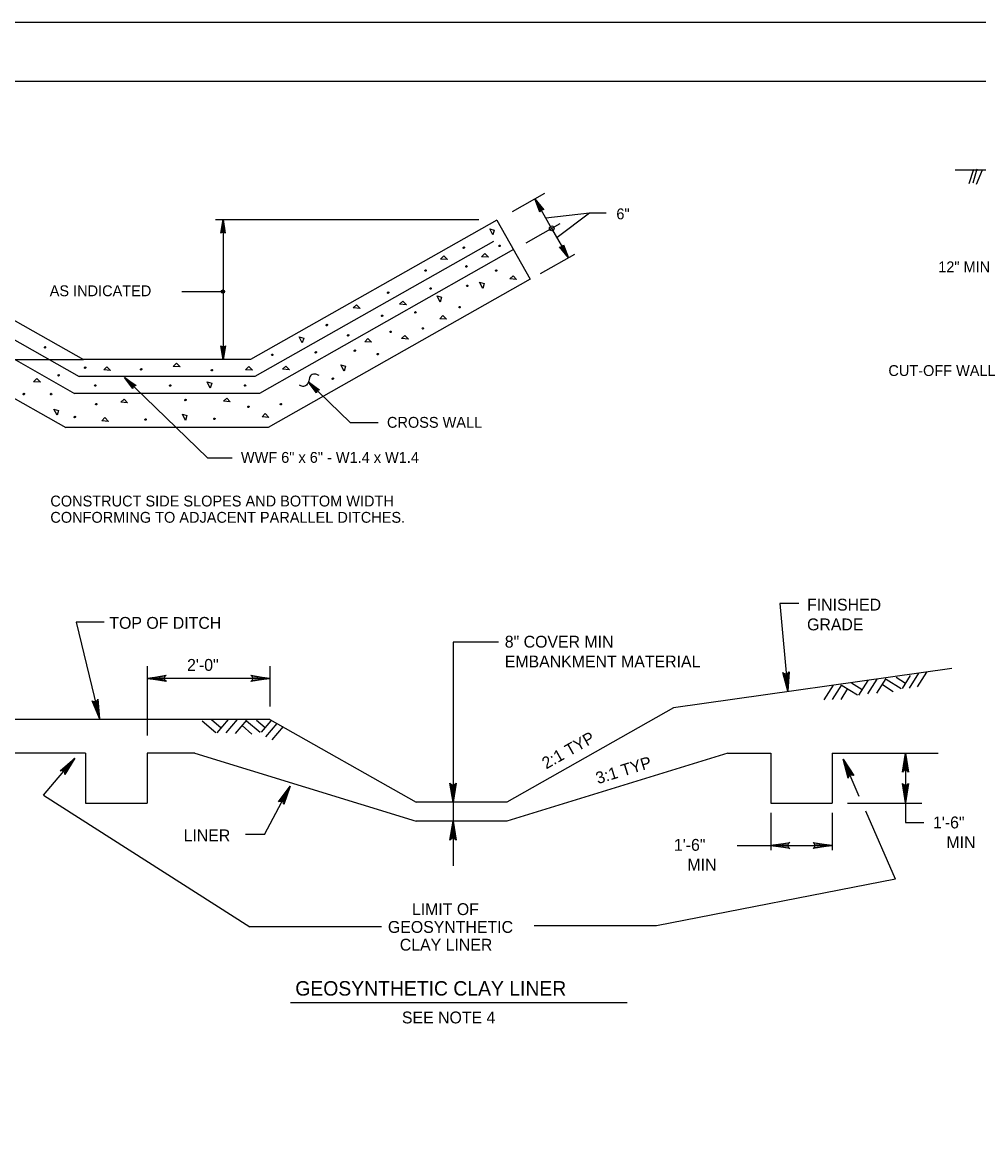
# Model space of a CAD drawing. Extents: x 5 to 910, y -47 to 547.
# Drawn here: x 364.1 to 606.1, y 266.3 to 547.5 of the extents above; entities that cross this region are included whole.
import ezdxf

# ---------------------------------------------------------------- set-up
doc = ezdxf.new("R2010")
doc.units = 0
for name, color, linetype in [('1', 7, 'Continuous'), ('2', 7, 'Continuous'), ('3', 7, 'Continuous'), ('PLT-BNDY', 7, 'Continuous')]:
    doc.layers.add(name, color=color, linetype=linetype)

msp = doc.modelspace()

# ---------------------------------------------------------------- linework, layer by layer
at = {"layer": '1'}
for p, q in [((623.41, 510.09), (600.07, 510.09)), ((604.72, 510.23), (603.5, 506.59)), ((605.54, 510.3), (604.53, 506.75)), ((606.89, 510.02), (605.36, 506.39))]:
    msp.add_line(p, q, dxfattribs=at)
msp.add_lwpolyline([(830.72, -31.53), (830.72, 532.47), (44.72, 532.47), (44.72, -31.53), (830.72, -31.53), (830.72, -5.17), (630.72, -5.17), (630.72, 59.51), (830.72, 59.51), (830.72, 88.47), (630.72, 88.47), (630.72, -31.53), (709.52, -31.53), (709.52, -5.17), (709.52, -31.53), (786.52, -31.53), (786.52, -5.17), (786.52, -17.48), (830.72, -17.48)], dxfattribs=at)
for points in [[(483.5, 494.91), (483.16, 493.68), (482.36, 495.23)], [(470.71, 488.35), (471.63, 487.41), (469.89, 487.55)], [(481.12, 488.94), (482.04, 488), (480.3, 488.14)], [(480.92, 481.37), (480.57, 480.13), (479.77, 481.69)], [(488.24, 483.34), (489.15, 482.4), (487.42, 482.53)], [(470.16, 477.91), (469.82, 476.68), (469.02, 478.23)], [(448.61, 476.01), (449.53, 475.08), (447.79, 475.21)], [(460.37, 476.95), (461.29, 476.01), (459.55, 476.15)], [(470.51, 473.27), (471.42, 472.33), (469.68, 472.47)], [(435.28, 467.57), (434.93, 466.34), (434.13, 467.89)], [(451.54, 467.46), (452.46, 466.52), (450.72, 466.66)], [(460.88, 468.24), (461.79, 467.3), (460.05, 467.43)], [(403.08, 461.21), (404, 460.27), (402.26, 460.41)], [(385.51, 460.32), (386.43, 459.38), (384.69, 459.52)], [(421.41, 460.37), (422.33, 459.43), (420.59, 459.56)], [(430.75, 460.5), (431.66, 459.56), (429.92, 459.7)], [(445.82, 460.48), (445.48, 459.24), (444.68, 460.8)], [(367.78, 457.35), (368.7, 456.41), (366.96, 456.54)], [(412.01, 456.16), (411.66, 454.92), (410.86, 456.48)], [(389.84, 452.13), (390.75, 451.19), (389.01, 451.33)], [(415.81, 452.4), (416.72, 451.47), (414.98, 451.6)], [(373.23, 449.27), (372.89, 448.03), (372.08, 449.59)], [(385.01, 447.44), (385.93, 446.5), (384.19, 446.64)], [(405.74, 447.99), (405.4, 446.75), (404.59, 448.31)], [(425.57, 448.45), (426.49, 447.51), (424.75, 447.64)]]:
    msp.add_lwpolyline(points, close=True, dxfattribs=at)
for centre in [(475.79, 490.45), (484.83, 490.89), (466.11, 484.64), (476.43, 485.71), (483.96, 484.64), (476.66, 480.77), (456.64, 479.06), (467.39, 480.11), (474.72, 475.37), (455.13, 473.22), (463.53, 474.09), (441.13, 470.87), (465.45, 470.02), (446.51, 468.26), (457.28, 469.13), (369.84, 465.24), (438.34, 463.96), (448.24, 464.39), (427.33, 463.32), (454.03, 463.52), (373.29, 458.15), (379.98, 460.09), (394.18, 459.66), (412.05, 459.45), (382.56, 455.56), (401.5, 455.56), (420.45, 455.58), (442.64, 457.3), (364.49, 453.41), (371.37, 453.41), (382.79, 450.83), (405.37, 451.9), (421.32, 450.18), (429.51, 450.85), (377.39, 447.6), (395.26, 446.96), (412.71, 447.16)]:
    msp.add_ellipse(centre, major_axis=(-0.048, -0.184), ratio=0.9, dxfattribs=at)
at = {"layer": '2'}
for p, q in [((496.2, 504.11), (488.01, 499.49)), ((493.78, 502.78), (498.01, 495.32)), ((507.6, 499.25), (511.82, 499.25)), ((318.05, 496.95), (379.59, 462.15)), ((413.01, 497.57), (479.55, 497.57)), ((414.89, 497.57), (414.89, 462.15)), ((484.17, 497.41), (421.8, 462.15)), ((484.17, 497.41), (492.61, 482.47)), ((500.11, 496.51), (491.44, 491.62)), ((498.01, 495.32), (502.24, 487.87)), ((313.84, 489.49), (377.32, 453.59)), ((318.43, 491.8), (378.44, 457.87)), ((483.32, 492.01), (422.94, 457.87)), ((488.38, 489.95), (424.06, 453.59)), ((503.75, 488.71), (495.08, 483.82)), ((309.6, 482.01), (375.08, 444.99)), ((492.61, 482.47), (426.31, 444.99)), ((404.46, 479.35), (414.89, 479.35)), ((290.57, 462.15), (379.59, 462.15)), ((421.8, 462.15), (379.59, 462.15)), ((421.8, 462.15), (379.59, 462.15)), ((421.8, 462.15), (379.59, 462.15)), ((422.94, 457.87), (378.44, 457.87)), ((389.95, 457.62), (410.93, 437.28)), ((436.44, 456.54), (447.03, 446.25)), ((424.06, 453.59), (377.32, 453.59)), ((426.31, 444.99), (375.08, 444.99)), ((447.03, 446.25), (454.15, 446.25)), ((410.93, 437.28), (417.22, 437.28)), ((560.52, 400.42), (555.74, 400.42)), ((555.74, 400.42), (557.73, 378.21)), ((384.78, 395.74), (377.74, 395.74)), ((484.56, 390.65), (473.06, 390.65)), ((473.06, 390.65), (473.06, 350.14)), ((395.67, 384.53), (395.67, 367.01)), ((426.73, 384.53), (426.73, 374.34)), ((599.2, 384), (528.85, 374)), ((426.73, 381.48), (395.67, 381.48)), ((528.85, 374), (486.65, 350.14)), ((426.73, 371.06), (357.43, 371.06)), ((426.73, 371.06), (463.73, 350.14)), ((380.12, 362.6), (357.86, 362.6)), ((380.12, 362.6), (380.12, 349.91)), ((395.67, 362.6), (395.67, 349.91)), ((407.78, 362.6), (395.67, 362.6)), ((407.78, 362.6), (463.73, 345.39)), ((542.6, 362.6), (486.65, 345.39)), ((542.6, 362.6), (553.43, 362.6)), ((553.43, 362.6), (553.43, 349.91)), ((568.98, 362.6), (595.77, 362.6)), ((568.98, 362.6), (568.98, 349.91)), ((587.54, 362.6), (587.54, 345.02)), ((380.12, 349.91), (395.67, 349.91)), ((486.65, 350.14), (463.73, 350.14)), ((473.06, 350.14), (473.06, 345.39)), ((553.43, 349.91), (568.98, 349.91)), ((572.88, 349.91), (591.66, 349.91)), ((553.43, 347.46), (553.43, 337.99)), ((568.98, 347.46), (568.98, 337.99)), ((486.65, 345.39), (463.73, 345.39)), ((473.06, 345.39), (473.06, 334.02)), ((587.54, 345.02), (592.18, 345.02)), ((425.4, 341.98), (420.52, 341.98)), ((544.9, 339.22), (568.98, 339.22)), ((454.95, 318.61), (421.68, 318.61)), ((524.51, 318.87), (493.6, 318.87)), ((517.1, 299.37), (431.97, 299.37))]:
    msp.add_line(p, q, dxfattribs=at)
msp.add_circle((414.85, 479.33), 0.409, dxfattribs=at)
at = {"layer": '3'}
for p, q in [((496.57, 497.97), (507.6, 499.25)), ((499.41, 493.06), (507.6, 499.25)), ((377.74, 395.74), (383.62, 371.29)), ((590.84, 382.77), (588.48, 379.03)), ((592.83, 383.07), (590.46, 379.33)), ((569.2, 379.77), (566.84, 376.03)), ((571.34, 379.87), (568.98, 376.13)), ((571.54, 379.71), (575.38, 377.28)), ((573.85, 380.34), (576.52, 378.64)), ((577.96, 380.94), (575.6, 377.2)), ((580.25, 381.27), (577.89, 377.53)), ((582.56, 381.47), (580.19, 377.73)), ((581.67, 379.91), (584.4, 378.18)), ((582.6, 381.32), (586.41, 378.91)), ((585.13, 381.82), (587.55, 380.29)), ((588.74, 382.17), (586.7, 378.95)), ((572.83, 378.89), (571.12, 376.18)), ((409.63, 370.77), (413.08, 367.82)), ((412, 371.06), (414.4, 369.01)), ((416.16, 371.07), (413.28, 367.71)), ((418.47, 371.07), (415.59, 367.71)), ((420.79, 370.93), (417.91, 367.57)), ((419.68, 369.52), (422.13, 367.41)), ((420.8, 370.77), (424.23, 367.84)), ((423.38, 370.91), (425.55, 369.04)), ((427, 370.73), (424.52, 367.84)), ((428.46, 370.07), (425.58, 366.71)), ((430.11, 369.28), (427.23, 365.92)), ((369.47, 351.91), (377.4, 361.33)), ((575.84, 351.64), (571.76, 361.01)), ((369.47, 351.91), (421.68, 318.61)), ((425.4, 341.98), (431.88, 354.18)), ((584.97, 330.71), (577.5, 347.85)), ((584.97, 330.71), (524.51, 318.87))]:
    msp.add_line(p, q, dxfattribs=at)
for points in [[(495.06, 499.69), (495.19, 499.92), (493.78, 502.78), (495.06, 499.69), (495.01, 499.46), (493.78, 502.78), (495.49, 500.08), (495.77, 500.11), (493.78, 502.78), (495.99, 500.01), (495.77, 500.11)], [(414.48, 494.25), (414.71, 494.36), (414.89, 497.57), (414.48, 494.25), (414.32, 494.07), (414.89, 497.57), (415.05, 494.36), (415.28, 494.25), (414.89, 497.57), (415.44, 494.07), (415.28, 494.25)], [(500.96, 490.95), (500.82, 490.73), (502.24, 487.87), (500.96, 490.95), (501.01, 491.18), (502.24, 487.87), (500.52, 490.57), (500.25, 490.54), (502.24, 487.87), (500.02, 490.63), (500.25, 490.54)], [(415.3, 465.47), (415.07, 465.35), (414.89, 462.15), (415.3, 465.47), (415.46, 465.65), (414.89, 462.15), (414.73, 465.35), (414.5, 465.47), (414.89, 462.15), (414.34, 465.65), (414.5, 465.47)], [(392.06, 455.01), (392.13, 455.26), (389.95, 457.62), (392.06, 455.01), (392.08, 454.78), (389.95, 457.62), (392.35, 455.52), (392.61, 455.61), (389.95, 457.62), (392.86, 455.58), (392.61, 455.61)], [(438.52, 453.94), (438.62, 454.19), (436.44, 456.54), (438.52, 453.94), (438.55, 453.71), (436.44, 456.54), (438.84, 454.44), (439.1, 454.51), (436.44, 456.54), (439.32, 454.51), (439.1, 454.51)], [(557.9, 382.86), (557.58, 382.66), (557.73, 378.21), (557.9, 382.86), (558.08, 383.11), (557.73, 378.21), (557.12, 382.61), (556.77, 382.75), (557.73, 378.21), (556.53, 382.98), (556.77, 382.75)], [(400.29, 380.91), (400.11, 381.24), (395.67, 381.48), (400.29, 380.91), (400.52, 380.7), (395.67, 381.48), (400.11, 381.7), (400.27, 382.03), (395.67, 381.48), (400.52, 382.26), (400.27, 382.03)], [(422.12, 382.06), (422.29, 381.73), (426.73, 381.48), (422.12, 382.06), (421.88, 382.27), (426.73, 381.48), (422.29, 381.27), (422.13, 380.94), (426.73, 381.48), (421.88, 380.71), (422.13, 380.94)], [(383.1, 375.91), (382.82, 375.67), (383.62, 371.29), (383.1, 375.91), (383.24, 376.19), (383.62, 371.29), (382.37, 375.55), (382.01, 375.63), (383.62, 371.29), (381.73, 375.83), (382.01, 375.63)], [(373.99, 358.18), (374.35, 358.09), (377.4, 361.33), (373.99, 358.18), (373.68, 358.13), (377.4, 361.33), (374.71, 357.8), (374.86, 357.46), (377.4, 361.33), (374.87, 357.13), (374.86, 357.46)], [(573.11, 356.56), (573.35, 356.85), (571.76, 361.01), (573.11, 356.56), (573.03, 356.26), (571.76, 361.01), (573.77, 357.04), (574.14, 357.03), (571.76, 361.01), (574.44, 356.89), (574.14, 357.03)], [(586.96, 357.99), (587.3, 358.16), (587.54, 362.6), (586.96, 357.99), (586.76, 357.75), (587.54, 362.6), (587.76, 358.16), (588.09, 358), (587.54, 362.6), (588.31, 357.75), (588.09, 358)], [(473.64, 354.76), (473.3, 354.58), (473.06, 350.14), (473.64, 354.76), (473.84, 354.99), (473.06, 350.14), (472.84, 354.58), (472.51, 354.74), (473.06, 350.14), (472.29, 354.99), (472.51, 354.74)], [(588.12, 354.62), (587.79, 354.45), (587.54, 350.01), (588.12, 354.62), (588.32, 354.86), (587.54, 350.01), (587.32, 354.45), (586.99, 354.61), (587.54, 350.01), (586.77, 354.86), (586.99, 354.61)], [(429.2, 350.38), (429.58, 350.38), (431.88, 354.18), (429.2, 350.38), (428.91, 350.27), (431.88, 354.18), (429.99, 350.16), (430.21, 349.86), (431.88, 354.18), (430.29, 349.54), (430.21, 349.86)], [(472.48, 340.77), (472.81, 340.95), (473.06, 345.39), (472.48, 340.77), (472.28, 340.54), (473.06, 345.39), (473.28, 340.95), (473.61, 340.79), (473.06, 345.39), (473.83, 340.54), (473.61, 340.79)], [(558.01, 338.64), (557.84, 338.97), (553.4, 339.22), (558.01, 338.64), (558.25, 338.44), (553.4, 339.22), (557.84, 339.44), (558, 339.77), (553.4, 339.22), (558.25, 339.99), (558, 339.77)], [(564.36, 339.8), (564.53, 339.46), (568.98, 339.22), (564.36, 339.8), (564.13, 340), (568.98, 339.22), (564.54, 339), (564.38, 338.67), (568.98, 339.22), (564.13, 338.45), (564.38, 338.67)]]:
    msp.add_lwpolyline(points, dxfattribs=at)
msp.add_circle((498.04, 495.33), 0.596, dxfattribs=at)
msp.add_spline([(439.21, 458.08), (438.64, 458.33), (437.43, 458.33), (436.72, 457.51), (436.6, 456.73), (436.17, 455.88), (435.25, 455.35), (434.84, 455.4), (434.25, 455.68)], degree=3, dxfattribs=at)
at = {"layer": 'PLT-BNDY'}
msp.add_lwpolyline([(4.72, 547.47), (845.72, 547.47), (845.72, -46.53), (4.72, -46.53)], close=True, dxfattribs=at)

# ---------------------------------------------------------------- texts
at = {"layer": '2'}
for s, p in [('CONSTRUCT SIDE SLOPES AND BOTTOM WIDTH', (371.19, 424.97)), ('CONFORMING TO ADJACENT PARALLEL DITCHES.', (371.19, 420.85))]:
    msp.add_text(s, height=2.7454, dxfattribs=at).set_placement(p)
at = {"layer": '3'}
for s, height, p in [('6"', 2.745, (514.38, 497.62)), ('12" MIN', 2.745, (595.8, 484.21)), ('AS INDICATED', 2.7454, (371.03, 478.16)), ('CUT-OFF WALL', 2.7454, (583.19, 457.98)), ('CROSS WALL', 2.745, (456.35, 444.88)), ('WWF 6" x 6" - W1.4 x W1.4 ', 2.7455, (419.4, 436.01)), ('FINISHED', 3, (562.62, 398.63)), ('TOP OF DITCH', 3, (386.12, 394.02)), ('GRADE', 3, (562.62, 393.63)), ('8" COVER MIN', 3, (486.15, 389.26)), ('2\'-0"', 3, (405.78, 383.39)), ('EMBANKMENT MATERIAL', 3, (486.15, 384.26)), ('1\'-6"', 3, (594.47, 343.53)), ('LINER', 3, (404.89, 340.26)), ('1\'-6"', 3, (528.93, 337.86)), ('MIN', 3, (597.88, 338.53)), ('MIN', 3, (532.35, 332.86)), ('LIMIT OF', 3, (462.66, 321.6)), ('GEOSYNTHETIC', 3, (456.59, 317.1)), ('CLAY LINER', 3, (459.59, 312.6)), ('GEOSYNTHETIC CLAY LINER', 3.6603, (433.16, 301.23)), ('SEE NOTE 4', 3, (460.13, 294.2))]:
    msp.add_text(s, height=height, dxfattribs=at).set_placement(p)
for s, rotation, p in [('2:1 TYP', 29.4798, (496.62, 358.43)), ('3:1 TYP', 17.1027, (509.7, 354.71))]:
    msp.add_text(s, height=3, rotation=rotation, dxfattribs=at).set_placement(p)

doc.saveas('drawing.dxf')
